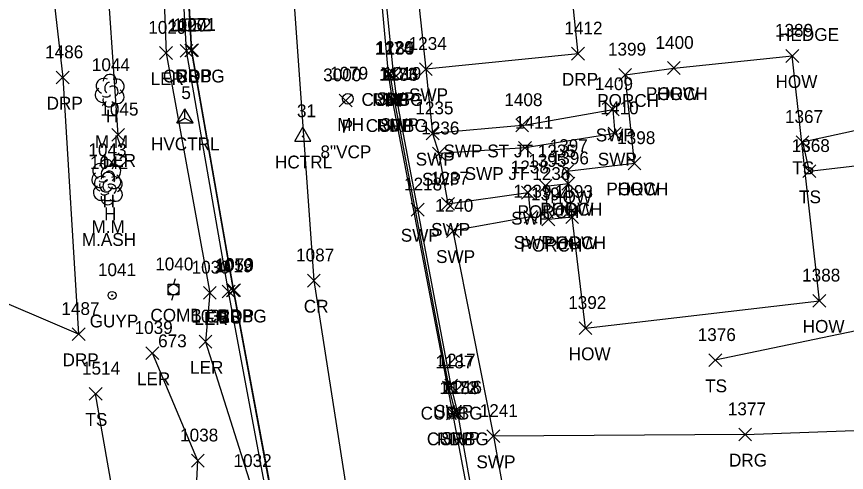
# Model space of a CAD drawing. Extents: x 462930 to 463548, y 29607 to 30453.
# Drawn here: x 463320.55 to 463360, y 30059.67 to 30081.35 of the extents above; entities that cross this region are included whole.
import ezdxf

# ---------------------------------------------------------------- set-up
doc = ezdxf.new("R2010")
doc.units = 0
for name, color, linetype in [('C_A', 7, 'Continuous'), ('C_I', 7, 'Continuous'), ('CPH', 7, 'Continuous'), ('CPSM', 7, 'Continuous'), ('D_A', 7, 'Continuous'), ('D_C', 7, 'Continuous'), ('D_I', 7, 'Continuous'), ('D_TIC', 7, 'Continuous'), ('L_A', 7, 'Continuous'), ('L_C', 7, 'Continuous'), ('L_I', 7, 'Continuous'), ('L_TIC', 7, 'Continuous'), ('LARO', 7, 'Continuous'), ('LBC', 7, 'Continuous'), ('LBF', 7, 'Continuous'), ('LELB', 7, 'Continuous'), ('LTD', 7, 'Continuous'), ('P_A', 7, 'Continuous'), ('P_I', 7, 'Continuous'), ('P_TIC', 7, 'Continuous'), ('PET', 7, 'Continuous'), ('PRC', 7, 'Continuous'), ('R_A', 7, 'Continuous'), ('R_I', 7, 'Continuous'), ('R_TIC', 7, 'Continuous'), ('RC', 7, 'Continuous'), ('RDG', 7, 'Continuous'), ('RDP', 7, 'Continuous'), ('RSW', 7, 'Continuous'), ('U_A', 7, 'Continuous'), ('U_C', 7, 'Continuous'), ('U_I', 7, 'Continuous'), ('UP', 7, 'Continuous'), ('UPGW', 7, 'Continuous'), ('UUMH', 7, 'Continuous')]:
    doc.layers.add(name, color=color, linetype=linetype)

msp = doc.modelspace()

# ---------------------------------------------------------------- linework, layer by layer
at = {"layer": 'CPH'}
for p, q in [((463333.776, 30075.435), (463334.157, 30076.095)), ((463334.538, 30075.435), (463334.157, 30076.095)), ((463334.157, 30075.655), (463334.157, 30075.655)), ((463333.776, 30075.435), (463334.538, 30075.435))]:
    msp.add_line(p, q, dxfattribs=at)
msp.add_circle((463334.157, 30075.655), 0.0254, dxfattribs=at)
at = {"layer": 'CPSM'}
for p, q in [((463328.179, 30076.298), (463328.56, 30076.958)), ((463328.941, 30076.298), (463328.56, 30076.958)), ((463328.56, 30076.518), (463328.56, 30076.958)), ((463328.179, 30076.298), (463328.56, 30076.518)), ((463328.179, 30076.298), (463328.941, 30076.298)), ((463328.56, 30076.518), (463328.56, 30076.518)), ((463328.56, 30076.518), (463328.941, 30076.298))]:
    msp.add_line(p, q, dxfattribs=at)
at = {"layer": 'D_TIC'}
for points in [[(463335.893, 30077.055), (463336.502, 30077.664)], [(463336.502, 30077.055), (463335.893, 30077.664)]]:
    msp.add_lwpolyline(points, dxfattribs=at)
at = {"layer": 'L_TIC'}
for points in [[(463327.355, 30079.316), (463327.965, 30079.926)], [(463327.965, 30079.316), (463327.355, 30079.926)], [(463328.324, 30079.423), (463328.934, 30080.033)], [(463328.934, 30079.423), (463328.324, 30080.033)], [(463357.125, 30079.177), (463357.735, 30079.787)], [(463357.735, 30079.177), (463357.125, 30079.787)], [(463351.495, 30078.6), (463352.105, 30079.21)], [(463352.105, 30078.6), (463351.495, 30079.21)], [(463351.495, 30078.6), (463352.105, 30079.21)], [(463352.105, 30078.6), (463351.495, 30079.21)], [(463349.185, 30078.278), (463349.795, 30078.888)], [(463349.795, 30078.278), (463349.185, 30078.888)], [(463325.075, 30075.426), (463325.685, 30076.036)], [(463325.685, 30075.426), (463325.075, 30076.036)], [(463357.612, 30075.075), (463358.222, 30075.685)], [(463358.222, 30075.075), (463357.612, 30075.685)], [(463349.622, 30074.069), (463350.232, 30074.679)], [(463350.232, 30074.069), (463349.622, 30074.679)], [(463349.622, 30074.069), (463350.232, 30074.679)], [(463350.232, 30074.069), (463349.622, 30074.679)], [(463346.412, 30073.693), (463347.022, 30074.303)], [(463347.022, 30073.693), (463346.412, 30074.303)], [(463357.933, 30073.694), (463358.543, 30074.304)], [(463358.543, 30073.694), (463357.933, 30074.304)], [(463345.394, 30072.987), (463346.004, 30073.597)], [(463346.004, 30072.987), (463345.394, 30073.597)], [(463346.481, 30073.105), (463347.091, 30073.715)], [(463347.091, 30073.105), (463346.481, 30073.715)], [(463346.481, 30073.105), (463347.091, 30073.715)], [(463347.091, 30073.105), (463346.481, 30073.715)], [(463345.531, 30071.393), (463346.141, 30072.003)], [(463346.141, 30071.393), (463345.531, 30072.003)], [(463346.658, 30071.51), (463347.268, 30072.12)], [(463347.268, 30071.51), (463346.658, 30072.12)], [(463346.658, 30071.51), (463347.268, 30072.12)], [(463347.268, 30071.51), (463346.658, 30072.12)], [(463329.439, 30067.908), (463330.049, 30068.518)], [(463330.049, 30067.908), (463329.439, 30068.518)], [(463330.328, 30067.97), (463330.938, 30068.58)], [(463330.938, 30067.97), (463330.328, 30068.58)], [(463358.415, 30067.532), (463359.025, 30068.142)], [(463359.025, 30067.532), (463358.415, 30068.142)], [(463347.294, 30066.227), (463347.904, 30066.837)], [(463347.904, 30066.227), (463347.294, 30066.837)], [(463329.232, 30065.583), (463329.842, 30066.193)], [(463329.842, 30065.583), (463329.232, 30066.193)], [(463326.705, 30065.039), (463327.315, 30065.649)], [(463327.315, 30065.039), (463326.705, 30065.649)], [(463353.467, 30064.703), (463354.077, 30065.313)], [(463354.077, 30064.703), (463353.467, 30065.313)], [(463324.006, 30063.104), (463324.616, 30063.714)], [(463324.616, 30063.104), (463324.006, 30063.714)], [(463328.867, 30059.925), (463329.477, 30060.535)], [(463329.477, 30059.925), (463328.867, 30060.535)]]:
    msp.add_lwpolyline(points, dxfattribs=at)
at = {"layer": 'LARO'}
for points in [[(463326.914, 30096.209), (463327.533, 30094.097), (463327.354, 30087.804), (463327.66, 30079.621), (463329.744, 30068.213), (463329.537, 30065.888), (463331.712, 30059.015), (463332.481, 30053.119), (463334.222, 30044.659), (463330.985, 30039.873), (463329.046, 30039.945), (463328.631, 30049.54), (463329.172, 30060.23), (463327.01, 30065.344)], [(463325.38, 30075.731), (463324.727, 30085.224), (463325.873, 30092.846)]]:
    msp.add_lwpolyline(points, dxfattribs=at)
at = {"layer": 'LBC'}
for points in [[(463351.8, 30078.905), (463357.43, 30079.482)], [(463358.72, 30067.837), (463357.43, 30079.482)], [(463347.599, 30066.532), (463346.963, 30071.815), (463346.786, 30073.41), (463346.717, 30073.998), (463349.927, 30074.374)], [(463347.599, 30066.532), (463358.72, 30067.837)]]:
    msp.add_lwpolyline(points, dxfattribs=at)
at = {"layer": 'LBF'}
for points in [[(463349.927, 30074.374), (463349.49, 30078.583), (463351.8, 30078.905)], [(463346.963, 30071.815), (463345.836, 30071.698), (463345.699, 30073.292), (463346.786, 30073.41)]]:
    msp.add_lwpolyline(points, dxfattribs=at)
at = {"layer": 'LELB'}
for points in [[(463338.373, 30022.22), (463340.767, 30011.24), (463345.965, 29995.767), (463346.937, 29987.36), (463347.521, 29987.525), (463346.646, 29996.093), (463342.063, 30011.435), (463339.344, 30022.565), (463336.301, 30037.573), (463333.414, 30053.384), (463330.633, 30068.275), (463328.629, 30079.728), (463328.086, 30089.487), (463328.627, 30097.184), (463330.299, 30105.361), (463329.682, 30105.522), (463327.994, 30097.289)], [(463378.516, 30048.648), (463377.397, 30060.388), (463373.955, 30062.949), (463378.381, 30068.216), (463380.763, 30073.646), (463377.061, 30079.056), (463368.749, 30077.741), (463357.917, 30075.38), (463358.238, 30073.999), (463362.431, 30074.488), (463362.024, 30068.592), (463364.125, 30068.673), (463364.188, 30075.412), (463369.759, 30071.787), (463365.468, 30065.245), (463360.854, 30066.478), (463353.772, 30065.008)], [(463325.855, 30054.564), (463324.311, 30063.409)]]:
    msp.add_lwpolyline(points, dxfattribs=at)
at = {"layer": 'LTD'}
for p, q in [((463324.975, 30077.845), (463324.975, 30077.845)), ((463324.975, 30077.845), (463324.975, 30077.845)), ((463324.813, 30073.8), (463324.813, 30073.8)), ((463324.813, 30073.8), (463324.813, 30073.8)), ((463324.887, 30073.19), (463324.887, 30073.19)), ((463324.887, 30073.19), (463324.887, 30073.19))]:
    msp.add_line(p, q, dxfattribs=at)
for centre in [(463324.989, 30078.282), (463324.827, 30074.237), (463324.901, 30073.627)]:
    msp.add_arc(centre, 0.319, 335.5272, 180.9563, dxfattribs=at)
for centre, major_axis, ratio, start_param, end_param in [((463324.734, 30078.048), (0.369, -0.156), 0.895232, 1.570796, 4.712389), ((463325.292, 30078.023), (-0.348, -0.147), 0.949671, 1.570796, 4.712389), ((463324.645, 30077.629), (0.178, -0.317), 0.959034, 3.141593, 6.283185), ((463324.911, 30077.985), (-0.063, -0.241), 0.645439, 3.141593, 6.283185), ((463325.127, 30077.794), (-0.152, 0.203), 0.989748, 3.141593, 6.283185), ((463325.28, 30077.591), (-0.332, 0.241), 0.841452, 1.570796, 4.712389), ((463324.835, 30077.616), (-0.19, -0.025), 0.423636, 0, 3.141593), ((463324.975, 30077.388), (0.081, 0.323), 0.942809, 1.570796, 4.712389), ((463324.572, 30074.003), (0.369, -0.156), 0.895232, 1.570796, 4.712389), ((463325.13, 30073.978), (-0.348, -0.147), 0.949671, 1.570796, 4.712389), ((463324.749, 30073.94), (-0.063, -0.241), 0.645439, 3.141593, 6.283185), ((463324.965, 30073.749), (-0.152, 0.203), 0.989748, 3.141593, 6.283185), ((463324.483, 30073.584), (0.178, -0.317), 0.959034, 3.141593, 6.283185), ((463324.646, 30073.393), (0.369, -0.156), 0.895232, 1.570796, 4.712389), ((463324.673, 30073.571), (-0.19, -0.025), 0.423636, 0, 3.141593), ((463324.823, 30073.33), (-0.063, -0.241), 0.645439, 3.141593, 6.283185), ((463325.118, 30073.546), (-0.332, 0.241), 0.841452, 1.570796, 4.712389), ((463325.204, 30073.368), (-0.348, -0.147), 0.949671, 1.570796, 4.712389), ((463324.557, 30072.974), (0.178, -0.317), 0.959034, 3.141593, 6.283185), ((463324.813, 30073.343), (0.081, 0.323), 0.942809, 1.570796, 4.712389), ((463325.039, 30073.139), (-0.152, 0.203), 0.989748, 3.141593, 6.283185), ((463325.192, 30072.936), (-0.332, 0.241), 0.841452, 1.570796, 4.712389), ((463324.887, 30072.733), (0.081, 0.323), 0.942809, 1.570796, 4.712389), ((463324.747, 30072.961), (-0.19, -0.025), 0.423636, 0, 3.141593)]:
    msp.add_ellipse(centre, major_axis=major_axis, ratio=ratio, start_param=start_param, end_param=end_param, dxfattribs=at)
at = {"layer": 'P_TIC'}
for points in [[(463328.585, 30079.455), (463329.195, 30080.065)], [(463329.195, 30079.455), (463328.585, 30080.065)], [(463337.922, 30078.318), (463338.532, 30078.928)], [(463338.532, 30078.318), (463337.922, 30078.928)], [(463338.127, 30077.094), (463338.737, 30077.704)], [(463338.737, 30077.094), (463338.127, 30077.704)], [(463334.381, 30068.491), (463334.991, 30069.101)], [(463334.991, 30068.491), (463334.381, 30069.101)], [(463330.582, 30068.034), (463331.192, 30068.644)], [(463331.192, 30068.034), (463330.582, 30068.644)], [(463340.996, 30062.178), (463341.606, 30062.788)], [(463341.606, 30062.178), (463340.996, 30062.788)]]:
    msp.add_lwpolyline(points, dxfattribs=at)
at = {"layer": 'PET'}
for points in [[(463374.338, 29956.391), (463367.555, 29969.533), (463365.556, 29974.625), (463364.583, 29976.896), (463356.695, 29995.475), (463352.505, 30009.098), (463350.167, 30017.966), (463347.98, 30027.115), (463347.733, 30028.32), (463346.051, 30037.294), (463343.907, 30048.483), (463342.761, 30054.643), (463342.551, 30055.85), (463341.301, 30062.483), (463338.432, 30077.399), (463338.227, 30078.623), (463337.48, 30086.968), (463337.479, 30088.196), (463338.474, 30099.226), (463339.751, 30104.374), (463341.961, 30110.783)], [(463349.052, 29990.82), (463346.99, 29996.409), (463342.314, 30011.546), (463339.633, 30022.646), (463336.631, 30037.644), (463333.669, 30053.397), (463330.887, 30068.339), (463328.89, 30079.76), (463328.357, 30089.522), (463328.892, 30097.183), (463330.561, 30105.3)]]:
    msp.add_lwpolyline(points, dxfattribs=at)
at = {"layer": 'PRC'}
msp.add_lwpolyline([(463337.978, 30112.385), (463335.087, 30099.771), (463333.576, 30084.385), (463334.686, 30068.796), (463337.03, 30053.748), (463339.908, 30038.01), (463343.632, 30023.045), (463346.617, 30012.904), (463351.044, 29997.524), (463354.76, 29987.177), (463360.584, 29974.202), (463367.548, 29960.534), (463374.695, 29948.349)], dxfattribs=at)
at = {"layer": 'R_TIC'}
for points in [[(463328.545, 30079.439), (463329.155, 30080.049)], [(463329.155, 30079.439), (463328.545, 30080.049)], [(463346.939, 30079.283), (463347.549, 30079.893)], [(463347.549, 30079.283), (463346.939, 30079.893)], [(463339.708, 30078.548), (463340.318, 30079.158)], [(463340.318, 30078.548), (463339.708, 30079.158)], [(463322.443, 30078.15), (463323.053, 30078.76)], [(463323.053, 30078.15), (463322.443, 30078.76)], [(463337.991, 30078.325), (463338.601, 30078.935)], [(463338.601, 30078.325), (463337.991, 30078.935)], [(463338.16, 30078.358), (463338.77, 30078.968)], [(463338.77, 30078.358), (463338.16, 30078.968)], [(463338.197, 30077.084), (463338.807, 30077.694)], [(463338.807, 30077.084), (463338.197, 30077.694)], [(463338.323, 30077.126), (463338.933, 30077.736)], [(463338.933, 30077.126), (463338.323, 30077.736)], [(463348.587, 30076.635), (463349.197, 30077.245)], [(463349.197, 30076.635), (463348.587, 30077.245)], [(463344.282, 30075.876), (463344.892, 30076.486)], [(463344.892, 30075.876), (463344.282, 30076.486)], [(463340.026, 30075.485), (463340.636, 30076.095)], [(463340.636, 30075.485), (463340.026, 30076.095)], [(463348.682, 30075.488), (463349.292, 30076.098)], [(463349.292, 30075.488), (463348.682, 30076.098)], [(463340.324, 30074.531), (463340.934, 30075.141)], [(463340.934, 30074.531), (463340.324, 30075.141)], [(463344.422, 30074.802), (463345.032, 30075.412)], [(463345.032, 30074.802), (463344.422, 30075.412)], [(463344.564, 30072.677), (463345.174, 30073.287)], [(463345.174, 30072.677), (463344.564, 30073.287)], [(463340.758, 30072.145), (463341.368, 30072.755)], [(463341.368, 30072.145), (463340.758, 30072.755)], [(463339.317, 30071.865), (463339.927, 30072.475)], [(463339.927, 30071.865), (463339.317, 30072.475)], [(463344.688, 30071.525), (463345.298, 30072.135)], [(463345.298, 30071.525), (463344.688, 30072.135)], [(463340.995, 30070.851), (463341.605, 30071.461)], [(463341.605, 30070.851), (463340.995, 30071.461)], [(463330.54, 30068.023), (463331.15, 30068.633)], [(463331.15, 30068.023), (463330.54, 30068.633)], [(463323.199, 30065.941), (463323.809, 30066.551)], [(463323.809, 30065.941), (463323.199, 30066.551)], [(463340.906, 30063.491), (463341.516, 30064.101)], [(463341.516, 30063.491), (463340.906, 30064.101)], [(463340.803, 30063.403), (463341.413, 30064.013)], [(463341.413, 30063.403), (463340.803, 30064.013)], [(463341.099, 30062.181), (463341.709, 30062.791)], [(463341.709, 30062.181), (463341.099, 30062.791)], [(463341.224, 30062.201), (463341.834, 30062.811)], [(463341.834, 30062.201), (463341.224, 30062.811)], [(463342.914, 30061.089), (463343.524, 30061.699)], [(463343.524, 30061.089), (463342.914, 30061.699)], [(463354.883, 30061.17), (463355.493, 30061.78)], [(463355.493, 30061.17), (463354.883, 30061.78)]]:
    msp.add_lwpolyline(points, dxfattribs=at)
at = {"layer": 'RC'}
for points in [[(463330.433, 30105.335), (463330.506, 30105.311), (463328.851, 30097.179), (463328.319, 30089.513), (463328.85, 30079.744), (463330.845, 30068.328), (463333.629, 30053.397), (463336.583, 30037.649), (463339.548, 30022.613), (463342.224, 30011.501), (463346.871, 29996.398), (463346.791, 29996.353)], [(463338.296, 30078.63), (463338.502, 30077.389), (463341.108, 30063.708), (463341.404, 30062.486)]]:
    msp.add_lwpolyline(points, dxfattribs=at)
at = {"layer": 'RDG'}
for points in [[(463355.188, 30061.475), (463366.856, 30061.901), (463368.547, 30056.261), (463358.377, 30057.19)], [(463355.188, 30061.475), (463343.219, 30061.394)]]:
    msp.add_lwpolyline(points, dxfattribs=at)
at = {"layer": 'RDP'}
for points in [[(463329.61, 30107.203), (463326.001, 30103.02), (463321.75, 30087.148), (463322.748, 30078.455), (463323.504, 30066.246), (463318.638, 30068.319), (463319.452, 30074.807), (463317.191, 30075.893), (463318.57, 30082.354), (463317.087, 30083.2)], [(463347.244, 30079.588), (463346.77, 30084.176), (463346.776, 30086.931)], [(463347.244, 30079.588), (463340.013, 30078.853)]]:
    msp.add_lwpolyline(points, dxfattribs=at)
at = {"layer": 'RSW'}
for points in [[(463342.697, 30055.906), (463341.529, 30062.506), (463341.211, 30063.796), (463339.622, 30072.17), (463338.628, 30077.431), (463338.465, 30078.663), (463337.643, 30086.947), (463337.707, 30088.204), (463338.63, 30099.17), (463339.961, 30104.318)], [(463340.994, 30103.946), (463340.038, 30098.879), (463339.394, 30093.997), (463344.79, 30093.902), (463344.842, 30092.794), (463339.225, 30092.816), (463339.128, 30087.087), (463340.013, 30078.853), (463340.331, 30075.79), (463340.629, 30074.836), (463341.063, 30072.45), (463344.869, 30072.982), (463344.993, 30071.83), (463341.3, 30071.156), (463343.219, 30061.394), (463344.068, 30056.729)], [(463344.587, 30076.181), (463348.892, 30076.94), (463348.987, 30075.793), (463344.727, 30075.107)], [(463344.587, 30076.181), (463340.331, 30075.79)], [(463344.727, 30075.107), (463340.629, 30074.836)]]:
    msp.add_lwpolyline(points, dxfattribs=at)
at = {"layer": 'UP'}
for p, q in [((463328.091, 30068.876), (463328.015, 30068.622)), ((463327.761, 30068.114), (463327.761, 30068.622)), ((463327.761, 30068.622), (463328.269, 30068.622)), ((463328.269, 30068.622), (463328.269, 30068.114)), ((463328.269, 30068.114), (463327.761, 30068.114)), ((463327.939, 30067.86), (463328.015, 30068.114)), ((463328.015, 30068.368), (463328.015, 30068.368))]:
    msp.add_line(p, q, dxfattribs=at)
msp.add_circle((463328.015, 30068.368), 0.254, dxfattribs=at)
at = {"layer": 'UPGW'}
for radius in [0.191, 0.0254]:
    msp.add_circle((463325.092, 30068.093), radius, dxfattribs=at)
at = {"layer": 'UUMH'}
for p, q in [((463336.299, 30077.442), (463336.299, 30077.442)), ((463336.553, 30077.442), (463336.553, 30077.442))]:
    msp.add_line(p, q, dxfattribs=at)
msp.add_circle((463336.299, 30077.442), 0.254, dxfattribs=at)

# ---------------------------------------------------------------- texts
at = {"layer": 'C_A'}
for s, p in [('HVCTRL', (463326.942, 30074.994)), ('HCTRL', (463332.837, 30074.131))]:
    msp.add_text(s, height=0.6096, dxfattribs=at).set_placement(p)
at = {"layer": 'C_I'}
for s, height, p in [('5', 0.61, (463328.387, 30077.432)), ('31', 0.6096, (463333.883, 30076.569))]:
    msp.add_text(s, height=height, dxfattribs=at).set_placement(p)
at = {"layer": 'D_A'}
msp.add_text('P', height=0.61, dxfattribs=at).set_placement((463336.008, 30075.836))
at = {"layer": 'D_C'}
msp.add_text('8"VCP', height=0.6096, dxfattribs=at).set_placement((463335, 30074.616))
at = {"layer": 'D_I'}
msp.add_text('3000', height=0.6096, dxfattribs=at).set_placement((463335.129, 30078.274))
at = {"layer": 'L_A'}
for s, height, p in [('HEDGE', 0.6096, (463356.755, 30080.195)), ('LER', 0.6096, (463326.923, 30078.097)), ('BS', 0.6096, (463328.154, 30078.204)), ('HOW', 0.6096, (463356.633, 30077.958)), ('PORCH', 0.6096, (463350.466, 30077.381)), ('HOW', 0.6096, (463351.003, 30077.381)), ('PORCH', 0.6096, (463348.156, 30077.059)), ('H', 0.61, (463324.802, 30076.321)), ('LER', 0.6096, (463324.643, 30074.207)), ('TS', 0.6096, (463357.432, 30073.856)), ('PORCH', 0.6096, (463348.593, 30072.85)), ('HOW', 0.6096, (463349.13, 30072.85)), ('H', 0.61, (463324.64, 30072.276)), ('HOW', 0.6096, (463345.92, 30072.474)), ('TS', 0.6096, (463357.753, 30072.475)), ('PORCH', 0.6096, (463344.365, 30071.768)), ('PORCH', 0.6096, (463345.452, 30071.886)), ('HOW', 0.6096, (463345.989, 30071.886)), ('H', 0.61, (463324.714, 30071.666)), ('PORCH', 0.6096, (463344.502, 30070.174)), ('PORCH', 0.6096, (463345.629, 30070.291)), ('HOW', 0.6096, (463346.166, 30070.291)), ('LER', 0.6096, (463329.007, 30066.689)), ('BS', 0.6096, (463330.158, 30066.751)), ('HOW', 0.6096, (463357.923, 30066.313)), ('HOW', 0.6096, (463346.802, 30065.008)), ('LER', 0.6096, (463328.8, 30064.364)), ('LER', 0.6096, (463326.273, 30063.82)), ('TS', 0.6096, (463353.287, 30063.484)), ('TS', 0.6096, (463323.826, 30061.885))]:
    msp.add_text(s, height=height, dxfattribs=at).set_placement(p)
at = {"layer": 'L_C'}
for s, p in [('M.M', (463324.274, 30075.102)), ('M.M', (463324.112, 30071.057)), ('M.ASH', (463323.653, 30070.447))]:
    msp.add_text(s, height=0.6096, dxfattribs=at).set_placement(p)
at = {"layer": 'L_I'}
for s, p in [('1029', (463326.813, 30080.535)), ('1020', (463327.758, 30080.642)), ('1389', (463356.607, 30080.396)), ('1400', (463350.929, 30079.819)), ('1400', (463350.929, 30079.819)), ('1399', (463348.667, 30079.497)), ('1044', (463324.13, 30078.759)), ('1045', (463324.535, 30076.645)), ('1367', (463357.082, 30076.294)), ('1398', (463349.106, 30075.288)), ('1398', (463349.106, 30075.288)), ('1397', (463345.896, 30074.912)), ('1368', (463357.403, 30074.913)), ('1043', (463323.968, 30074.714)), ('1042', (463324.042, 30074.104)), ('1395', (463344.878, 30074.206)), ('1396', (463345.948, 30074.324)), ('1396', (463345.948, 30074.324)), ('1394', (463345.015, 30072.612)), ('1393', (463346.142, 30072.729)), ('1393', (463346.142, 30072.729)), ('1030', (463328.873, 30069.127)), ('1019', (463329.959, 30069.189)), ('1388', (463357.899, 30068.751)), ('1392', (463346.778, 30067.446)), ('1031', (463328.865, 30066.802)), ('1039', (463326.163, 30066.258)), ('1376', (463352.934, 30065.922)), ('1514', (463323.663, 30064.323)), ('1038', (463328.327, 30061.144)), ('1032', (463330.867, 30059.929))]:
    msp.add_text(s, height=0.6096, dxfattribs=at).set_placement(p)
at = {"layer": 'P_A'}
for s, p in [('RDP', (463328.124, 30078.236)), ('RDP', (463337.461, 30077.099)), ('RDP', (463337.666, 30075.875)), ('CR', (463334.208, 30067.272)), ('RDP', (463330.121, 30066.815)), ('RDP', (463340.535, 30060.959))]:
    msp.add_text(s, height=0.6096, dxfattribs=at).set_placement(p)
at = {"layer": 'P_I'}
for s, p in [('1071', (463328.218, 30080.674)), ('1174', (463337.579, 30079.537)), ('1173', (463337.784, 30078.313)), ('1087', (463333.841, 30069.71)), ('1070', (463330.016, 30069.253)), ('1172', (463340.653, 30063.397))]:
    msp.add_text(s, height=0.6096, dxfattribs=at).set_placement(p)
at = {"layer": 'R_A'}
for s, p in [('CURBG', (463327.504, 30078.22)), ('DRP', (463346.478, 30078.064)), ('SWP', (463339.209, 30077.329)), ('DRP', (463321.982, 30076.931)), ('CURBG', (463336.95, 30077.106)), ('SWP', (463337.661, 30077.139)), ('CURBG', (463337.156, 30075.865)), ('SWP', (463337.824, 30075.907)), ('SWP', (463348.088, 30075.416)), ('SWP ST JT 1235', (463340.848, 30074.657)), ('SWP', (463339.527, 30074.266)), ('SWP', (463348.183, 30074.269)), ('SWP', (463339.825, 30073.312)), ('SWP JT 1236', (463341.854, 30073.583)), ('SWP', (463344.065, 30071.458)), ('SWP', (463338.818, 30070.646)), ('SWP', (463340.259, 30070.926)), ('SWP', (463344.189, 30070.306)), ('SWP', (463340.496, 30069.632)), ('CURBG', (463329.499, 30066.804)), ('DRP', (463322.738, 30064.722)), ('SWP', (463340.407, 30062.272)), ('CURBG', (463339.762, 30062.184)), ('CURBG', (463340.058, 30060.962)), ('SWP', (463340.725, 30060.982)), ('DRG', (463354.422, 30059.951)), ('SWP', (463342.415, 30059.87))]:
    msp.add_text(s, height=0.6096, dxfattribs=at).set_placement(p)
at = {"layer": 'R_I'}
for s, p in [('1052', (463328.005, 30080.658)), ('1412', (463346.596, 30080.502)), ('1234', (463339.192, 30079.767)), ('1486', (463321.91, 30079.369)), ('1220', (463337.618, 30079.577)), ('1185', (463337.648, 30079.544)), ('1186', (463337.837, 30078.303)), ('1219', (463337.978, 30078.345)), ('1409', (463348.045, 30077.854)), ('1408', (463343.742, 30077.095)), ('1235', (463339.51, 30076.704)), ('1410', (463348.313, 30076.707)), ('1236', (463339.791, 30075.75)), ('1411', (463344.252, 30076.021)), ('1238', (463344.048, 30073.896)), ('1237', (463340.242, 30073.364)), ('1218', (463338.974, 30073.084)), ('1239', (463344.17, 30072.744)), ('1240', (463340.453, 30072.07)), ('1053', (463330, 30069.242)), ('1487', (463322.683, 30067.16)), ('1187', (463340.46, 30064.622)), ('1217', (463340.563, 30064.71)), ('1188', (463340.756, 30063.4)), ('1216', (463340.864, 30063.42)), ('1241', (463342.571, 30062.308)), ('1377', (463354.367, 30062.389))]:
    msp.add_text(s, height=0.6096, dxfattribs=at).set_placement(p)
at = {"layer": 'U_A'}
for s, p in [('MH', (463335.8, 30075.918)), ('COMB', (463326.913, 30066.844)), ('GUYP', (463324.029, 30066.569))]:
    msp.add_text(s, height=0.6096, dxfattribs=at).set_placement(p)
at = {"layer": 'U_C'}
msp.add_text('673', height=0.6096, dxfattribs=at).set_placement((463327.281, 30065.625))
at = {"layer": 'U_I'}
for s, p in [('1079', (463335.452, 30078.356)), ('1041', (463324.42, 30069.007)), ('1040', (463327.144, 30069.282))]:
    msp.add_text(s, height=0.6096, dxfattribs=at).set_placement(p)

doc.saveas('drawing.dxf')
